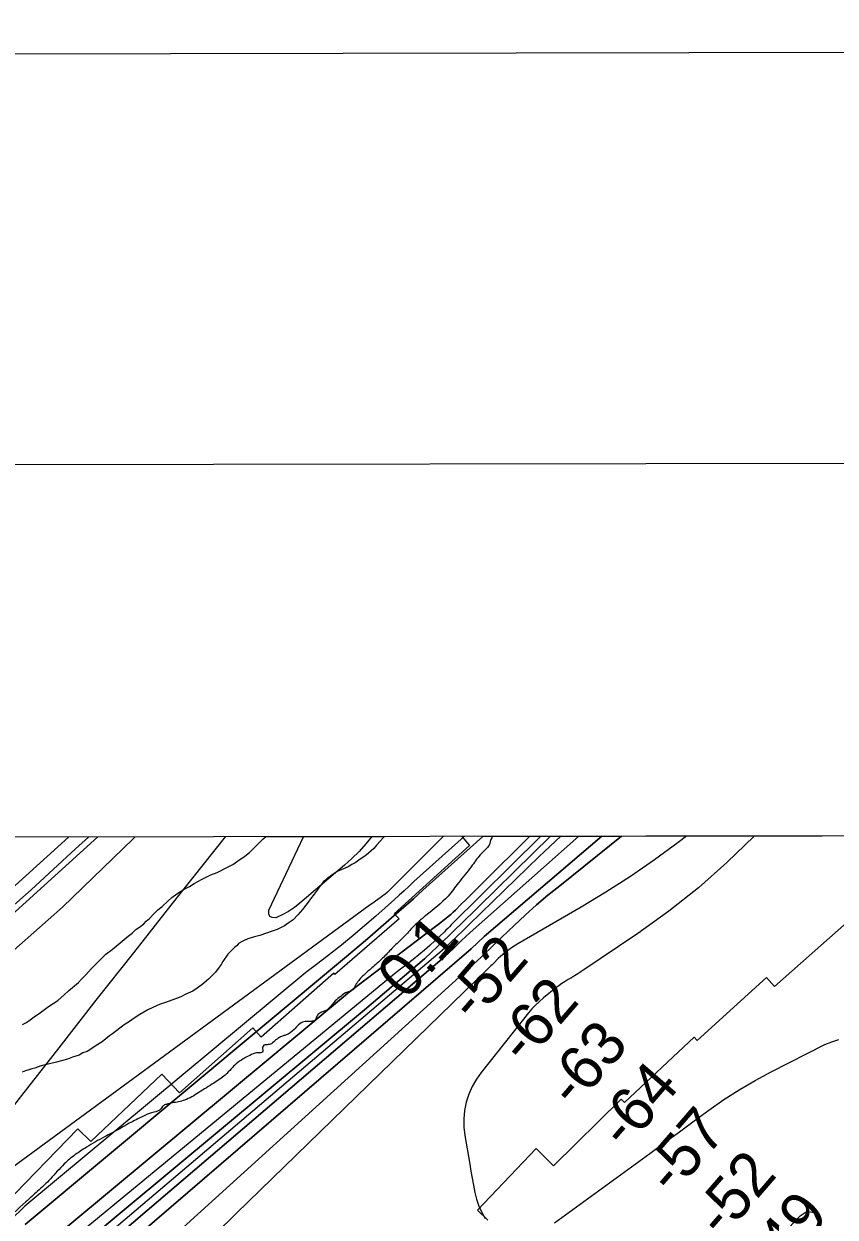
# Model space of a CAD drawing. Extents: x 3324125 to 3362000, y 600753 to 626151.
# Drawn here: x 3335086 to 3336321, y 623752 to 625567 of the extents above; entities that cross this region are included whole.
import ezdxf

# ---------------------------------------------------------------- set-up
doc = ezdxf.new("R2010")
doc.units = 0
for name, color, linetype in [('G-ANNO-NPLT', 7, 'Continuous'), ('V-ANNO-SYMB', 7, 'Continuous'), ('V-FLOD-BASE', 7, 'Continuous'), ('V-GRID-FRAM', 7, 'Continuous'), ('V-LEVE-TOET', 7, 'Continuous'), ('V-RIVR-EDGE', 7, 'Continuous'), ('V-RIVR-RANG', 7, 'Continuous'), ('V-RRAP-RVMT', 7, 'Continuous'), ('V-SITE-VEGE', 7, 'Continuous'), ('V-SURV-LINE', 7, 'Continuous'), ('V-TOPO-DPTH', 7, 'Continuous'), ('V-TOPO-MAJR', 7, 'Continuous'), ('V-TOPO-MINR', 7, 'Continuous'), ('V-TOPO-WATR', 7, 'Continuous')]:
    doc.layers.add(name, color=color, linetype=linetype)

msp = doc.modelspace()

# ---------------------------------------------------------------- linework, layer by layer
at = {"layer": 'G-ANNO-NPLT'}
msp.add_lwpolyline([(3324750.5, 601336.7), (3361417.2, 601400.7), (3361375, 625567.3), (3324708.4, 625503.3)], close=True, dxfattribs=at)
at = {"layer": 'V-ANNO-SYMB'}
msp.add_lwpolyline([(3327499.6, 601966.6), (3360582.7, 602024.3), (3360542.7, 624940.8), (3327459.6, 624883.1), (3327499.6, 601966.6)], dxfattribs=at)
at = {"layer": 'V-FLOD-BASE'}
msp.add_lwpolyline([(3334548.7, 623752.8), (3334629.3, 623828.7), (3334694.8, 623886.6), (3334805.7, 623986), (3334903.7, 624071.5), (3334946.6, 624111.3), (3334993.7, 624155.4), (3335045, 624203.7), (3335097.3, 624249.9), (3335164.8, 624312.5), (3335184.9, 624330.4)], dxfattribs=at)
at = {"layer": 'V-GRID-FRAM'}
msp.add_lwpolyline([(3328210, 624318.2), (3328233.8, 606134.5), (3359834, 606189.7), (3359794.3, 624373.3), (3328210, 624318.2)], dxfattribs=at)
at = {"layer": 'V-LEVE-TOET'}
msp.add_lwpolyline([(3334560.5, 623714.3), (3334617.6, 623766.9), (3334718.3, 623860.2), (3334885.2, 623999.3), (3335035.7, 624127.2), (3335145.4, 624223.5), (3335252.8, 624327.9), (3335255.7, 624330.5)], dxfattribs=at)
at = {"layer": 'V-RIVR-EDGE'}
msp.add_spline([(3335799.7, 624331.4), (3335798.3, 624329.3), (3335794.2, 624318), (3335789.1, 624311.4), (3335780.7, 624303.1), (3335767.1, 624285.2), (3335747.7, 624260.7), (3335731.9, 624240.7), (3335698.2, 624211.1), (3335677.3, 624192.2), (3335662.7, 624176.5), (3335646.5, 624160.8), (3335632.3, 624145.9), (3335615.8, 624131.3), (3335603.3, 624120), (3335592.3, 624106.9), (3335585, 624096.6), (3335578.8, 624094.5), (3335568.5, 624087.9), (3335560.1, 624081), (3335551.6, 624071.1), (3335543.6, 624065.3), (3335538.1, 624063.5), (3335533, 624059.1), (3335530.8, 624053.6), (3335527.8, 624050.7), (3335522.7, 624050), (3335516.1, 624049.7), (3335512.5, 624049.3), (3335497.5, 624037.6), (3335485.4, 624029.3), (3335478.4, 624027.1), (3335472.9, 624023.8), (3335468.5, 624020.5), (3335461.2, 624015.1), (3335455, 624014.4), (3335451.7, 624013.6), (3335449.5, 624010.7), (3335449.5, 624008.2), (3335450.2, 624006.3), (3335449.1, 624003), (3335446.9, 624002.3), (3335438.2, 624001.6), (3335427.5, 623996.9), (3335420.2, 623992.9), (3335409.6, 623985.2), (3335401.9, 623977.9), (3335392.7, 623968.4), (3335375.5, 623956.1), (3335352.8, 623941.9), (3335330.9, 623930.2), (3335312.6, 623925.9), (3335303.4, 623923.7), (3335298.3, 623921.5), (3335294.3, 623916.4), (3335290.6, 623913.9), (3335277.5, 623909.9), (3335265.4, 623904.4), (3335244.1, 623893.5), (3335232.4, 623886.6), (3335209, 623874.2), (3335181.9, 623858.6), (3335164.7, 623847.3), (3335147.9, 623833.1), (3335127, 623810.5), (3335107.2, 623791.5), (3335089.6, 623775.5), (3335053, 623741.5), (3335042, 623729.5), (3335028.8, 623711.3), (3335018.1, 623697.8), (3335015.6, 623695.6), (3335013.4, 623695.2), (3335009, 623694.1), (3335004.6, 623690.5), (3334995.8, 623678.5), (3334991.7, 623671.9), (3334991.4, 623666), (3334990.6, 623658.4), (3334993.5, 623650.7), (3334993.9, 623647.7), (3334996.4, 623642.6), (3334993.1, 623636.8), (3334983.6, 623621.5), (3334967.1, 623601.8), (3334950.9, 623585), (3334929, 623567.9)], degree=3, dxfattribs=at)
at = {"layer": 'V-RRAP-RVMT'}
for p, q in [((3336505, 624332.7), (3335752.8, 624331.3)), ((3335752.8, 624331.3), (3335764.3, 624317.3)), ((3335764.3, 624317.3), (3335650.1, 624213.7)), ((3335657.4, 624205.8), (3335559.8, 624121.2)), ((3335650.1, 624213.7), (3335657.4, 624205.8)), ((3336228.6, 624102.8), (3336338.7, 624200.4)), ((3335558, 624123.2), (3335447.3, 624026.1)), ((3335559.8, 624121.2), (3335558, 624123.2)), ((3336110.9, 624021), (3336216.3, 624116.7)), ((3336216.3, 624116.7), (3336228.6, 624102.8)), ((3335434.7, 624040.3), (3335323.2, 623941.2)), ((3335447.3, 624026.1), (3335434.7, 624040.3)), ((3336000.3, 623926.6), (3336106.2, 624026.1)), ((3336106.2, 624026.1), (3336110.9, 624021)), ((3335296.3, 623969.5), (3335188.5, 623867.4)), ((3335323.2, 623941.2), (3335296.3, 623969.5)), ((3335892.5, 623830.2), (3335995.4, 623931.8)), ((3335995.4, 623931.8), (3336000.3, 623926.6)), ((3335168.6, 623886.4), (3335057.5, 623771.9)), ((3335188.5, 623867.4), (3335168.6, 623886.4)), ((3335776.6, 623762.8), (3335866.2, 623856.4)), ((3335866.2, 623856.4), (3335892.5, 623830.2)), ((3335792.4, 623747.7), (3335776.6, 623762.8))]:
    msp.add_line(p, q, dxfattribs=at)
at = {"layer": 'V-SITE-VEGE'}
for p, q in [((3335450.2, 624327.4), (3335453.9, 624330.8)), ((3335453.9, 624330.8), (3335635, 624331.1)), ((3335635, 624331.1), (3335633, 624329.3)), ((3335429.6, 624307.1), (3335435.9, 624313)), ((3335435.9, 624313), (3335450.2, 624327.4)), ((3335618.7, 624313.2), (3335610.8, 624305.7)), ((3335622.9, 624318), (3335618.7, 624313.2)), ((3335629.3, 624324.5), (3335622.9, 624318)), ((3335633, 624329.3), (3335629.3, 624324.5)), ((3335411.6, 624293.7), (3335422.7, 624301.2)), ((3335422.7, 624301.2), (3335429.6, 624307.1)), ((3335599.7, 624297.7), (3335590.7, 624291.2)), ((3335605.5, 624301.4), (3335599.7, 624297.7)), ((3335610.8, 624305.7), (3335605.5, 624301.4)), ((3335370.9, 624272.7), (3335380.4, 624276.4)), ((3335380.4, 624276.4), (3335397.3, 624285.1)), ((3335397.3, 624285.1), (3335404.2, 624288.8)), ((3335404.2, 624288.8), (3335411.6, 624293.7)), ((3335563.2, 624277.8), (3335556.8, 624273.5)), ((3335580.1, 624285.3), (3335563.2, 624277.8)), ((3335585.4, 624288.5), (3335580.1, 624285.3)), ((3335590.7, 624291.2), (3335585.4, 624288.5)), ((3335338.6, 624255.4), (3335345.5, 624259.7)), ((3335345.5, 624259.7), (3335356.6, 624265.6)), ((3335356.6, 624265.6), (3335364, 624269.4)), ((3335364, 624269.4), (3335370.9, 624272.7)), ((3335540.5, 624259.5), (3335535.7, 624254.2)), ((3335542.6, 624262.7), (3335540.5, 624259.5)), ((3335545.2, 624264.9), (3335542.6, 624262.7)), ((3335549.4, 624268.6), (3335545.2, 624264.9)), ((3335553.1, 624270.8), (3335549.4, 624268.6)), ((3335556.8, 624273.5), (3335553.1, 624270.8)), ((3335311.6, 624238.2), (3335319, 624244.1)), ((3335319, 624244.1), (3335330.6, 624251.1)), ((3335330.6, 624251.1), (3335338.6, 624255.4)), ((3335528.4, 624243.5), (3335522.6, 624236.5)), ((3335532.6, 624249.4), (3335528.4, 624243.5)), ((3335535.7, 624254.2), (3335532.6, 624249.4)), ((3335290.5, 624219.5), (3335296.8, 624224.8)), ((3335296.8, 624224.8), (3335305.3, 624232.9)), ((3335305.3, 624232.9), (3335311.6, 624238.2)), ((3335515.7, 624226.9), (3335510.5, 624220)), ((3335518.9, 624231.2), (3335515.7, 624226.9)), ((3335522.6, 624236.5), (3335518.9, 624231.2)), ((3335272.5, 624202.3), (3335277.8, 624206.6)), ((3335277.8, 624206.6), (3335284.7, 624214.1)), ((3335284.7, 624214.1), (3335290.5, 624219.5)), ((3335496.2, 624204.5), (3335489.9, 624200.2)), ((3335503.1, 624212), (3335496.2, 624204.5)), ((3335506.8, 624216.2), (3335503.1, 624212)), ((3335510.5, 624220), (3335506.8, 624216.2)), ((3335251.4, 624184.1), (3335256.7, 624189.5)), ((3335256.7, 624189.5), (3335262.5, 624193.2)), ((3335262.5, 624193.2), (3335268.8, 624198.6)), ((3335268.8, 624198.6), (3335272.5, 624202.3)), ((3335464.5, 624187.2), (3335445.4, 624180.7)), ((3335471.9, 624190), (3335464.5, 624187.2)), ((3335483, 624195.3), (3335471.9, 624190)), ((3335489.9, 624200.2), (3335483, 624195.3)), ((3335229.7, 624167), (3335236.1, 624171.8)), ((3335236.1, 624171.8), (3335245.1, 624179.8)), ((3335245.1, 624179.8), (3335251.4, 624184.1)), ((3335413.1, 624168.3), (3335410.9, 624165.6)), ((3335417.8, 624171), (3335413.1, 624168.3)), ((3335421.5, 624173.1), (3335417.8, 624171)), ((3335427.4, 624175.3), (3335421.5, 624173.1)), ((3335437.4, 624178.6), (3335427.4, 624175.3)), ((3335445.4, 624180.7), (3335437.4, 624178.6)), ((3335204.9, 624146.1), (3335211.3, 624152)), ((3335211.3, 624152), (3335220.8, 624159.5)), ((3335220.8, 624159.5), (3335229.7, 624167)), ((3335396.7, 624152.2), (3335389.3, 624141)), ((3335406.7, 624162.4), (3335396.7, 624152.2)), ((3335410.9, 624165.6), (3335406.7, 624162.4)), ((3335189.1, 624130), (3335204.9, 624146.1)), ((3335383.6, 624132.5), (3335377.8, 624125)), ((3335386.7, 624136.7), (3335383.6, 624132.5)), ((3335389.3, 624141), (3335386.7, 624136.7)), ((3335169.6, 624109.2), (3335174.3, 624114)), ((3335174.3, 624114), (3335180.7, 624120.9)), ((3335180.7, 624120.9), (3335184.9, 624125.2)), ((3335184.9, 624125.2), (3335189.1, 624130)), ((3335367.2, 624114.3), (3335357.2, 624105.7)), ((3335377.8, 624125), (3335367.2, 624114.3)), ((3335147.9, 624090.4), (3335154.3, 624096.3)), ((3335154.3, 624096.3), (3335169.6, 624109.2)), ((3335343.4, 624096), (3335332.8, 624091.2)), ((3335350.3, 624100.4), (3335343.4, 624096)), ((3335357.2, 624105.7), (3335350.3, 624100.4)), ((3335124.1, 624072.7), (3335131, 624077)), ((3335131, 624077), (3335137.9, 624081.8)), ((3335137.9, 624081.8), (3335147.9, 624090.4)), ((3335300.5, 624078.2), (3335293.6, 624076)), ((3335318.5, 624084.7), (3335300.5, 624078.2)), ((3335325.4, 624087.4), (3335318.5, 624084.7)), ((3335332.8, 624091.2), (3335325.4, 624087.4)), ((3335104.1, 624058.2), (3335109.9, 624062)), ((3335109.9, 624062), (3335115.7, 624066.3)), ((3335115.7, 624066.3), (3335124.1, 624072.7)), ((3335262.9, 624060.4), (3335254.5, 624055)), ((3335275.1, 624067.4), (3335262.9, 624060.4)), ((3335282.5, 624071.2), (3335275.1, 624067.4)), ((3335293.6, 624076), (3335282.5, 624071.2)), ((3335084.5, 624045.3), (3335090.3, 624048.5)), ((3335090.3, 624048.5), (3335096.1, 624052.3)), ((3335096.1, 624052.3), (3335104.1, 624058.2)), ((3335239.1, 624044.8), (3335221.2, 624030.9)), ((3335247.1, 624049.7), (3335239.1, 624044.8)), ((3335254.5, 624055), (3335247.1, 624049.7)), ((3335216.9, 624028.2), (3335205.8, 624019.1)), ((3335221.2, 624030.9), (3335216.9, 624028.2)), ((3335182.6, 624004), (3335176.2, 624001.9)), ((3335198.9, 624014.8), (3335182.6, 624004)), ((3335205.8, 624019.1), (3335198.9, 624014.8)), ((3335135.9, 623987.8), (3335114.7, 623982.8)), ((3335152.9, 623992.7), (3335135.9, 623987.8)), ((3335160.3, 623995.4), (3335152.9, 623992.7)), ((3335170.4, 623998.6), (3335160.3, 623995.4)), ((3335176.2, 624001.9), (3335170.4, 623998.6)), ((3335088.7, 623974.7), (3335083.9, 623972.5)), ((3335094, 623976.3), (3335088.7, 623974.7)), ((3335098.8, 623977.9), (3335094, 623976.3)), ((3335103, 623979), (3335098.8, 623977.9)), ((3335109.9, 623981.2), (3335103, 623979)), ((3335114.7, 623982.8), (3335109.9, 623981.2))]:
    msp.add_line(p, q, dxfattribs=at)
at = {"layer": 'V-SURV-LINE'}
for points in [[(3334202, 623467.9), (3335154.4, 624330.4)], [(3335199.1, 624330.5), (3334222.2, 623445.6)]]:
    msp.add_lwpolyline(points, dxfattribs=at)
at = {"layer": 'V-TOPO-DPTH'}
for points in [[(3335088.4, 623741.1), (3335574.2, 624146.2), (3335609.2, 624175.8), (3335649.9, 624210.8), (3335664.6, 624223.6), (3335679.3, 624236.5), (3335693.7, 624249.6), (3335784.9, 624331.4), (3335856.4, 624331.5)], [(3335096.1, 623690.6), (3335582.1, 624094.8), (3335712.9, 624194.4), (3335716.9, 624197.4), (3335720.7, 624200.4), (3335724.6, 624203.4), (3335728.5, 624206.4), (3335732.3, 624209.5), (3335736.1, 624212.7), (3335739.7, 624216), (3335743.2, 624219.4), (3335752, 624228.1), (3335759.9, 624235.9), (3335767.7, 624243.7), (3335775.6, 624251.5), (3335783.5, 624259.3), (3335856.4, 624331.5)], [(3335856.4, 624331.5), (3335783.5, 624259.3), (3335775.6, 624251.5), (3335767.7, 624243.7), (3335759.9, 624235.9), (3335752, 624228.1), (3335743.2, 624219.4), (3335739.7, 624216), (3335736.1, 624212.7), (3335732.3, 624209.5), (3335728.5, 624206.4), (3335724.6, 624203.4), (3335720.7, 624200.4), (3335716.9, 624197.4), (3335712.9, 624194.4), (3335582.1, 624094.8), (3335096.1, 623690.6)], [(3335154.4, 623578.2), (3335781.7, 624147.4), (3335802.7, 624167.5), (3335823.7, 624187.6), (3335832.4, 624196), (3335849.2, 624211.7), (3335866.3, 624227.1), (3335883.9, 624241.9), (3335901.8, 624256.4), (3335995.9, 624331.8), (3337217.7, 624333.9)], [(3335966.1, 624331.7), (3335995.9, 624331.8), (3335901.8, 624256.4), (3335883.9, 624241.9), (3335866.3, 624227.1), (3335849.2, 624211.7), (3335832.4, 624196), (3335823.7, 624187.6), (3335802.7, 624167.5), (3335781.7, 624147.4), (3335154.4, 623578.2)], [(3335931.1, 624331.7), (3335966.1, 624331.7), (3335786.8, 624179.3), (3335767, 624160.2), (3335158.6, 623637.1)], [(3335158.6, 623637.1), (3335767, 624160.2), (3335786.8, 624179.3), (3335966.1, 624331.7)], [(3335163.5, 623700.5), (3335604.7, 624067.7), (3335696.2, 624144.9), (3335726.1, 624173.4), (3335732.2, 624179.3), (3335738.3, 624185.2), (3335744.3, 624191.1), (3335750.4, 624197), (3335888, 624331.6)], [(3335856.4, 624331.5), (3335888, 624331.6), (3335750.4, 624197), (3335744.3, 624191.1), (3335738.3, 624185.2), (3335732.2, 624179.3), (3335726.1, 624173.4), (3335696.2, 624144.9), (3335604.7, 624067.7), (3335163.5, 623700.5)], [(3335888, 624331.6), (3335931.1, 624331.7), (3335765.4, 624185.2), (3335752.5, 624172.8), (3335739.5, 624160.4), (3335726.6, 624148.1), (3335163.6, 623668.2)], [(3335163.6, 623668.2), (3335726.6, 624148.1), (3335739.5, 624160.4), (3335752.5, 624172.8), (3335765.4, 624185.2), (3335931.1, 624331.7)]]:
    msp.add_lwpolyline(points, dxfattribs=at)
at = {"layer": 'V-TOPO-MAJR'}
for points in [[(3336095.1, 624331.9), (3336094.6, 624331.5), (3336081.9, 624321.9), (3336046.1, 624295.7), (3336009.6, 624270.4), (3335972.2, 624246.5), (3335934.2, 624223.5), (3335838, 624167.9), (3335834, 624165.4), (3335830.1, 624162.9), (3335826.3, 624160.3), (3335822.5, 624157.5), (3335818.8, 624154.6), (3335815.2, 624151.6), (3335811.8, 624148.6), (3335808.3, 624145.4), (3335800.8, 624138.1), (3335798.8, 624136.2), (3335796.8, 624134.3), (3335794.8, 624132.3), (3335792.8, 624130.4), (3335409.7, 623757.6), (3335377.9, 623726.6)], [(3335615.7, 624331.1), (3335606.6, 624319.9), (3335596.5, 624308.5), (3335585.7, 624297.8), (3335574.4, 624287.5), (3335506.6, 624229.9), (3335498, 624223.4), (3335489.1, 624217.3), (3335479.7, 624212.2), (3335469.9, 624207.7), (3335464.4, 624208), (3335460.6, 624209.7), (3335459, 624213.7), (3335459.1, 624219.1), (3335503.3, 624312.5), (3335512.1, 624330.9)], [(3335392.7, 624330.7), (3335310.3, 624226.6), (3335253.2, 624154.4), (3335196.2, 624082), (3335139.4, 624009.5), (3335082.7, 623937), (3335005.8, 623838.4), (3334987.6, 623815), (3334969.5, 623791.6), (3334951.5, 623768.2), (3334933.5, 623744.7)], [(3336215.4, 623698.7), (3336267.8, 623754.2), (3336278.5, 623761.3), (3336288.3, 623759.5), (3336293.7, 623747.9)]]:
    msp.add_lwpolyline(points, dxfattribs=at)
at = {"layer": 'V-TOPO-MINR'}
for points in [[(3335724.5, 624331.3), (3335643, 624249.7), (3335639.5, 624246.7), (3335636, 624243.7), (3335632.4, 624240.8), (3335628.8, 624238), (3335625, 624235.3), (3335621.3, 624232.6), (3335617.4, 624230), (3335613.6, 624227.5), (3335012, 623785.9), (3335004.2, 623777), (3334996.5, 623768.1), (3334989.1, 623758.9), (3334981.7, 623749.7)], [(3335756.6, 624331.4), (3335679.8, 624262.7), (3335672.5, 624255.7), (3335665.1, 624248.8), (3335657.7, 624242), (3335650.2, 624235.2), (3335622, 624210.2), (3335604.8, 624195.2), (3335587.4, 624180.4), (3335569.6, 624166), (3335551.7, 624151.9), (3335533.5, 624138), (3335515.3, 624124.3), (3335087.9, 623769), (3335066.1, 623747.7)], [(3335784.9, 624331.4), (3335693.7, 624249.6), (3335679.3, 624236.5), (3335664.6, 624223.6), (3335649.9, 624210.8), (3335609.2, 624175.8), (3335574.2, 624146.2), (3335088.4, 623741.1)], [(3335995.9, 624331.8), (3335901.8, 624256.4), (3335883.9, 624241.9), (3335866.3, 624227.1), (3335849.2, 624211.7), (3335832.4, 624196), (3335823.7, 624187.6), (3335802.7, 624167.5), (3335781.7, 624147.4), (3335154.4, 623578.2)], [(3335966.1, 624331.7), (3335786.8, 624179.3), (3335767, 624160.2), (3335158.6, 623637.1)], [(3335903.3, 624331.6), (3335870.6, 624300.6), (3335764.2, 624197.3), (3335754.8, 624188.2), (3335745.3, 624179), (3335735.8, 624169.9), (3335726.3, 624160.8), (3335163.5, 623683)], [(3335888, 624331.6), (3335750.4, 624197), (3335744.3, 624191.1), (3335738.3, 624185.2), (3335732.2, 624179.3), (3335726.1, 624173.4), (3335696.2, 624144.9), (3335604.7, 624067.7), (3335163.5, 623700.5)], [(3335931.1, 624331.7), (3335765.4, 624185.2), (3335752.5, 624172.8), (3335739.5, 624160.4), (3335726.6, 624148.1), (3335163.6, 623668.2)], [(3335873.2, 624331.6), (3335736.7, 624196.6), (3335734, 624193.9), (3335731.3, 624191.2), (3335728.5, 624188.6), (3335725.8, 624185.9), (3335712.2, 624173), (3335704.2, 624165.5), (3335696, 624158.2), (3335687.6, 624151.2), (3335679, 624144.3), (3335670.3, 624137.6), (3335661.6, 624130.9), (3335652.9, 624124.3), (3335163.9, 623721.7)], [(3336197.8, 624332.1), (3336197.6, 624331.9), (3336156.1, 624291.6), (3336113.1, 624253.2), (3336067.8, 624217.6), (3336020.9, 624183.8), (3335934.1, 624125.6), (3335929.3, 624122.4), (3335924.5, 624119.4), (3335919.7, 624116.4), (3335914.8, 624113.6), (3335909.9, 624110.6), (3335905.2, 624107.6), (3335900.5, 624104.3), (3335896, 624100.8), (3335876.9, 624085.6), (3335870.8, 624080.4), (3335864.9, 624074.9), (3335859.5, 624069.1), (3335854.3, 624063), (3335782.4, 623972.4), (3335775.1, 623961.9), (3335768.7, 623950.9), (3335763.7, 623939.2), (3335759.6, 623927), (3335757.1, 623914.4), (3335755.7, 623901.8), (3335755.9, 623889.1), (3335757.3, 623876.4), (3335764.8, 623832.9), (3335766.6, 623822.1), (3335768.6, 623811.4), (3335770.6, 623800.6), (3335772.6, 623789.8), (3335775.3, 623779.3), (3335778.7, 623769.1), (3335783.3, 623759.4), (3335788.6, 623749.9)], [(3335893.8, 623743.5), (3336038.7, 623849.2), (3336061.3, 623865.6), (3336083.8, 623882), (3336106.3, 623898.5), (3336128.8, 623915), (3336151.6, 623930.9), (3336175, 623946), (3336199, 623960), (3336223.5, 623973.2), (3336305.2, 624014.8), (3336315.8, 624019.1), (3336326.6, 624022.2)]]:
    msp.add_lwpolyline(points, dxfattribs=at)
at = {"layer": 'V-TOPO-WATR'}
msp.add_lwpolyline([(3335856.4, 624331.5), (3335783.5, 624259.3), (3335775.6, 624251.5), (3335767.7, 624243.7), (3335759.9, 624235.9), (3335752, 624228.1), (3335743.2, 624219.4), (3335739.7, 624216), (3335736.1, 624212.7), (3335732.3, 624209.5), (3335728.5, 624206.4), (3335724.6, 624203.4), (3335720.7, 624200.4), (3335716.9, 624197.4), (3335712.9, 624194.4), (3335582.1, 624094.8), (3335096.1, 623690.6)], dxfattribs=at)

# ---------------------------------------------------------------- texts
at = {"layer": 'V-RIVR-RANG'}
for s, rotation, p in [('0.1', 48.8483, (3335669.2, 624080.8)), ('-52', 49.1326, (3335772, 624045.9)), ('-62', 49.1326, (3335848.8, 623981.8)), ('-63', 49.1326, (3335923.9, 623915.8)), ('-64', 49.1326, (3336001.6, 623852.8)), ('-57', 49.1326, (3336073.8, 623783.4)), ('-52', 49.1326, (3336149.3, 623717.8)), ('-49', 49.1326, (3336228, 623656))]:
    msp.add_text(s, height=67, rotation=rotation, dxfattribs=at).set_placement(p)

doc.saveas('drawing.dxf')
